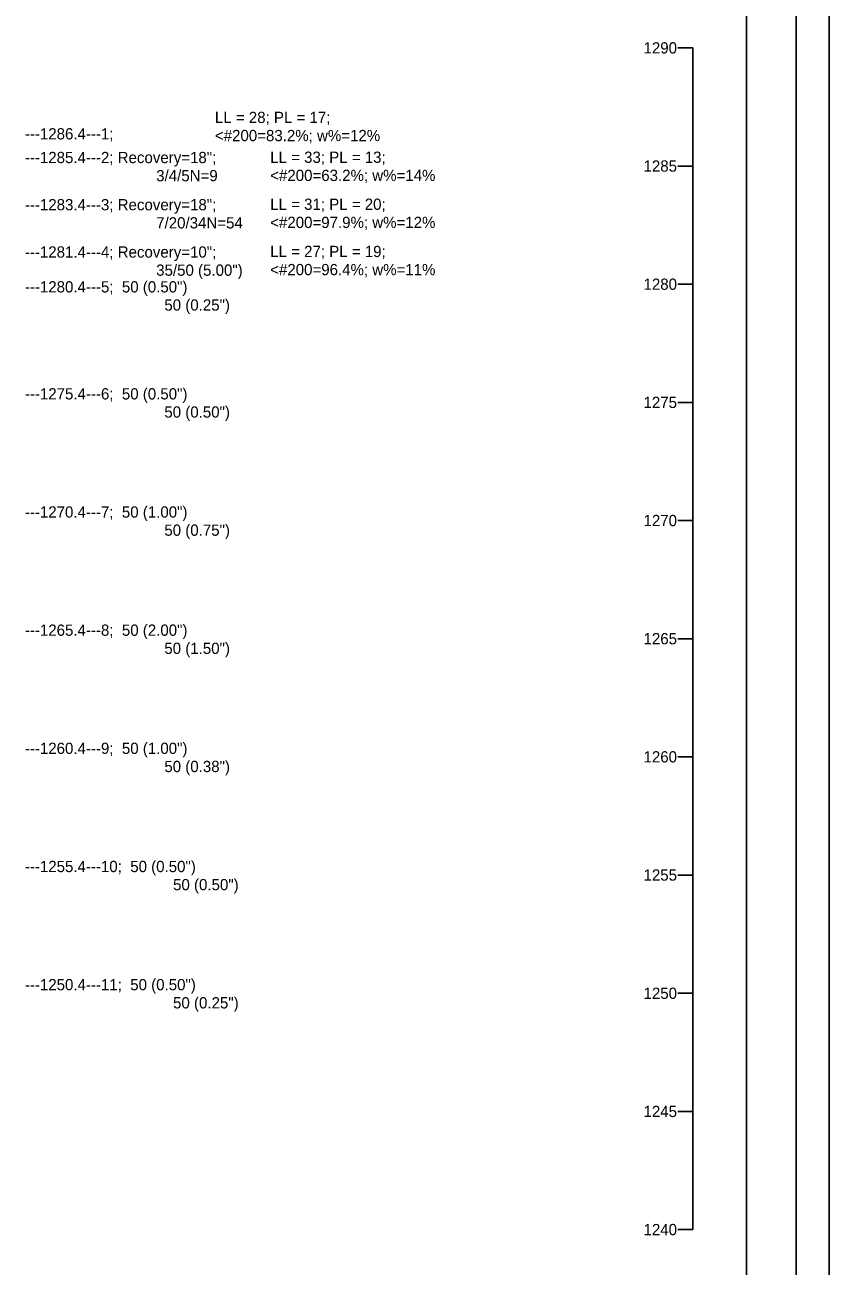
# Model space of a CAD drawing. Extents: x -2 to 138, y 24 to 58.
# Drawn here: x 33.76 to 42.62, y 36.46 to 50.14 of the extents above; entities that cross this region are included whole.
import ezdxf

# ---------------------------------------------------------------- set-up
doc = ezdxf.new("R2010")
doc.units = 0
for name, color, linetype in [('SHT_Plot_Shape_Full', 7, 'Continuous'), ('SHT_Plot_Shape_Half', 7, 'Continuous'), ('SHT_Sheet_Border', 7, 'Continuous')]:
    doc.layers.add(name, color=color, linetype=linetype)

msp = doc.modelspace()

# ---------------------------------------------------------------- linework, layer by layer
msp.add_line((41.123, 36.866), (41.123, 49.887))
for points in [[(41.123, 49.887), (40.956, 49.887)], [(41.123, 48.585), (40.956, 48.585)], [(41.123, 47.283), (40.956, 47.283)], [(41.123, 45.981), (40.956, 45.981)], [(41.123, 44.679), (40.956, 44.679)], [(41.123, 43.377), (40.956, 43.377)], [(41.123, 42.075), (40.956, 42.075)], [(41.123, 40.773), (40.956, 40.773)], [(41.123, 39.47), (40.956, 39.47)], [(41.123, 38.168), (40.956, 38.168)], [(41.123, 36.866), (40.956, 36.866)]]:
    msp.add_lwpolyline(points)
at = {"layer": 'SHT_Plot_Shape_Full'}
msp.add_lwpolyline([(6.624, 53.971), (42.624, 53.971), (42.624, 29.971), (6.624, 29.971)], close=True, dxfattribs=at)
at = {"layer": 'SHT_Plot_Shape_Half'}
msp.add_lwpolyline([(8.262, 53.146), (42.262, 53.146), (42.262, 31.146), (8.262, 31.146)], close=True, dxfattribs=at)
at = {"layer": 'SHT_Sheet_Border'}
msp.add_lwpolyline([(10.212, 52.646), (41.712, 52.646), (41.712, 31.646), (10.212, 31.646)], close=True, dxfattribs=at)

# ---------------------------------------------------------------- texts
for s, p in [('1290', (40.579, 49.825)), ('LL = 28; PL = 17;', (35.857, 49.059)), ('---1286.4---1;', (33.763, 48.878)), ('<#200=83.2%; w%=12%', (35.857, 48.859)), ('---1285.4---2; Recovery=18";', (33.763, 48.617)), ('LL = 33; PL = 13;', (36.466, 48.62)), ('1285', (40.579, 48.523)), ('3/4/5N=9', (35.21, 48.417)), ('<#200=63.2%; w%=14%', (36.466, 48.42)), ('---1283.4---3; Recovery=18";', (33.763, 48.097)), ('LL = 31; PL = 20;', (36.466, 48.102)), ('7/20/34N=54', (35.21, 47.897)), ('<#200=97.9%; w%=12%', (36.466, 47.902)), ('---1281.4---4; Recovery=10";', (33.763, 47.576)), ('LL = 27; PL = 19;', (36.466, 47.582)), ('35/50 (5.00")', (35.21, 47.376)), ('<#200=96.4%; w%=11%', (36.466, 47.382)), ('1280', (40.579, 47.221)), ('---1280.4---5;  50 (0.50")', (33.763, 47.192)), ('50 (0.25")', (35.3, 46.992)), ('---1275.4---6;  50 (0.50")', (33.763, 46.013)), ('1275', (40.579, 45.919)), ('50 (0.50")', (35.3, 45.813)), ('---1270.4---7;  50 (1.00")', (33.763, 44.711)), ('1270', (40.579, 44.617)), ('50 (0.75")', (35.3, 44.511)), ('---1265.4---8;  50 (2.00")', (33.763, 43.409)), ('1265', (40.579, 43.315)), ('50 (1.50")', (35.3, 43.209)), ('---1260.4---9;  50 (1.00")', (33.763, 42.107)), ('1260', (40.579, 42.013)), ('50 (0.38")', (35.3, 41.907)), ('---1255.4---10;  50 (0.50")', (33.763, 40.805)), ('1255', (40.579, 40.711)), ('50 (0.50")', (35.396, 40.605)), ('---1250.4---11;  50 (0.50")', (33.763, 39.503)), ('1250', (40.579, 39.408)), ('50 (0.25")', (35.396, 39.303)), ('1245', (40.579, 38.106)), ('1240', (40.579, 36.804))]:
    msp.add_text(s, height=0.124).set_placement(p)

doc.saveas('drawing.dxf')
